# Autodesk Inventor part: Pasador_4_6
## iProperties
Created: 2008-01
Part Number: Pasador_4_6
Material: ABS Plastic
Document SubType Name: Modeling
Designer: eruiz-tagle
Mass: 0.309351 g
Surface Area: 4.77348 cm^2
Volume: 0.291841 cm^3
Density: 1.06 g/cm^3
Company: COMGRAP
Title: CURSO INVENTOR
Author: Esteban
Comments: Esta pieza fue creada en el curso de inventor
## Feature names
1. Derived Body1 [Tagging]
